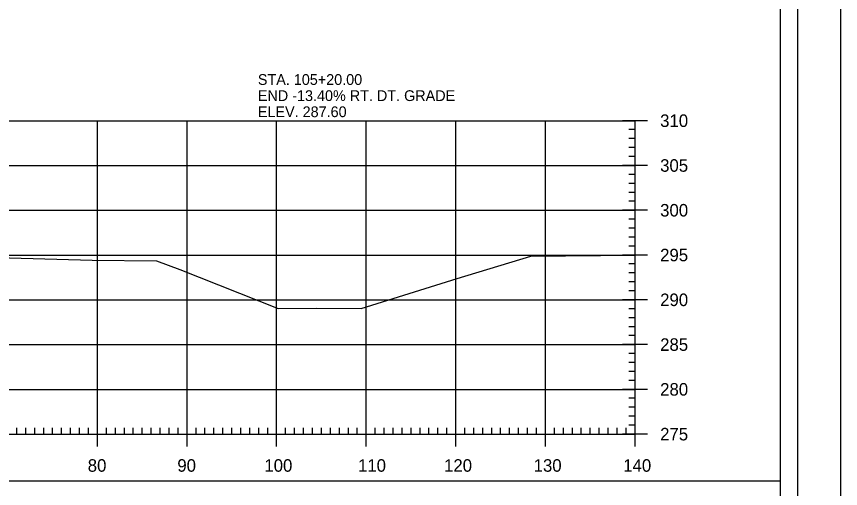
# Model space of a CAD drawing. Extents: x 1368713 to 1370673, y 380279 to 380950.
# Drawn here: x 1370223.2 to 1370315.2, y 380418.3 to 380471.1 of the extents above; entities that cross this region are included whole.
import ezdxf

# ---------------------------------------------------------------- set-up
doc = ezdxf.new("R2010")
doc.units = 0
for name, color, linetype in [('Notes', 7, 'Continuous'), ('R_Axis', 7, 'Continuous'), ('R_Axis Annot', 7, 'Continuous'), ('R_Border', 7, 'Continuous'), ('R_Exist Surface', 7, 'Continuous'), ('R_Grid', 7, 'Continuous'), ('R_No Plot', 7, 'Continuous')]:
    doc.layers.add(name, color=color, linetype=linetype)

msp = doc.modelspace()

# ---------------------------------------------------------------- linework, layer by layer
at = {"layer": 'R_Axis'}
for p, q in [((1370293.683, 380459.416), (1370290.883, 380459.416)), ((1370292.283, 380424.416), (1370292.283, 380459.416)), ((1370292.283, 380458.416), (1370291.583, 380458.416)), ((1370292.283, 380457.416), (1370291.583, 380457.416)), ((1370292.283, 380456.416), (1370291.583, 380456.416)), ((1370292.283, 380455.416), (1370291.583, 380455.416)), ((1370293.683, 380454.416), (1370290.883, 380454.416)), ((1370292.283, 380453.416), (1370291.583, 380453.416)), ((1370292.283, 380452.416), (1370291.583, 380452.416)), ((1370292.283, 380451.416), (1370291.583, 380451.416)), ((1370292.283, 380450.416), (1370291.583, 380450.416)), ((1370293.683, 380449.416), (1370290.883, 380449.416)), ((1370292.283, 380448.416), (1370291.583, 380448.416)), ((1370292.283, 380447.416), (1370291.583, 380447.416)), ((1370292.283, 380446.416), (1370291.583, 380446.416)), ((1370292.283, 380445.416), (1370291.583, 380445.416)), ((1370293.683, 380444.416), (1370290.883, 380444.416)), ((1370292.283, 380443.416), (1370291.583, 380443.416)), ((1370292.283, 380442.416), (1370291.583, 380442.416)), ((1370292.283, 380441.416), (1370291.583, 380441.416)), ((1370292.283, 380440.416), (1370291.583, 380440.416)), ((1370293.683, 380439.416), (1370290.883, 380439.416)), ((1370292.283, 380438.416), (1370291.583, 380438.416)), ((1370292.283, 380437.416), (1370291.583, 380437.416)), ((1370292.283, 380436.416), (1370291.583, 380436.416)), ((1370292.283, 380435.416), (1370291.583, 380435.416)), ((1370293.683, 380434.416), (1370290.883, 380434.416)), ((1370292.283, 380433.416), (1370291.583, 380433.416)), ((1370292.283, 380432.416), (1370291.583, 380432.416)), ((1370292.283, 380431.416), (1370291.583, 380431.416)), ((1370292.283, 380430.416), (1370291.583, 380430.416)), ((1370293.683, 380429.416), (1370290.883, 380429.416)), ((1370292.283, 380428.416), (1370291.583, 380428.416)), ((1370292.283, 380427.416), (1370291.583, 380427.416)), ((1370292.283, 380426.416), (1370291.583, 380426.416)), ((1370232.283, 380423.016), (1370232.283, 380425.816)), ((1370242.283, 380423.016), (1370242.283, 380425.816)), ((1370252.283, 380423.016), (1370252.283, 380425.816)), ((1370262.283, 380423.016), (1370262.283, 380425.816)), ((1370272.283, 380423.016), (1370272.283, 380425.816)), ((1370282.283, 380423.016), (1370282.283, 380425.816)), ((1370292.283, 380425.416), (1370291.583, 380425.416)), ((1370292.283, 380423.016), (1370292.283, 380425.816)), ((1370012.283, 380424.416), (1370292.283, 380424.416)), ((1370223.283, 380424.416), (1370223.283, 380425.116)), ((1370224.283, 380424.416), (1370224.283, 380425.116)), ((1370225.283, 380424.416), (1370225.283, 380425.116)), ((1370226.283, 380424.416), (1370226.283, 380425.116)), ((1370227.283, 380424.416), (1370227.283, 380425.116)), ((1370228.283, 380424.416), (1370228.283, 380425.116)), ((1370229.283, 380424.416), (1370229.283, 380425.116)), ((1370230.283, 380424.416), (1370230.283, 380425.116)), ((1370231.283, 380424.416), (1370231.283, 380425.116)), ((1370233.283, 380424.416), (1370233.283, 380425.116)), ((1370234.283, 380424.416), (1370234.283, 380425.116)), ((1370235.283, 380424.416), (1370235.283, 380425.116)), ((1370236.283, 380424.416), (1370236.283, 380425.116)), ((1370237.283, 380424.416), (1370237.283, 380425.116)), ((1370238.283, 380424.416), (1370238.283, 380425.116)), ((1370239.283, 380424.416), (1370239.283, 380425.116)), ((1370240.283, 380424.416), (1370240.283, 380425.116)), ((1370241.283, 380424.416), (1370241.283, 380425.116)), ((1370243.283, 380424.416), (1370243.283, 380425.116)), ((1370244.283, 380424.416), (1370244.283, 380425.116)), ((1370245.283, 380424.416), (1370245.283, 380425.116)), ((1370246.283, 380424.416), (1370246.283, 380425.116)), ((1370247.283, 380424.416), (1370247.283, 380425.116)), ((1370248.283, 380424.416), (1370248.283, 380425.116)), ((1370249.283, 380424.416), (1370249.283, 380425.116)), ((1370250.283, 380424.416), (1370250.283, 380425.116)), ((1370251.283, 380424.416), (1370251.283, 380425.116)), ((1370253.283, 380424.416), (1370253.283, 380425.116)), ((1370254.283, 380424.416), (1370254.283, 380425.116)), ((1370255.283, 380424.416), (1370255.283, 380425.116)), ((1370256.283, 380424.416), (1370256.283, 380425.116)), ((1370257.283, 380424.416), (1370257.283, 380425.116)), ((1370258.283, 380424.416), (1370258.283, 380425.116)), ((1370259.283, 380424.416), (1370259.283, 380425.116)), ((1370260.283, 380424.416), (1370260.283, 380425.116)), ((1370261.283, 380424.416), (1370261.283, 380425.116)), ((1370263.283, 380424.416), (1370263.283, 380425.116)), ((1370264.283, 380424.416), (1370264.283, 380425.116)), ((1370265.283, 380424.416), (1370265.283, 380425.116)), ((1370266.283, 380424.416), (1370266.283, 380425.116)), ((1370267.283, 380424.416), (1370267.283, 380425.116)), ((1370268.283, 380424.416), (1370268.283, 380425.116)), ((1370269.283, 380424.416), (1370269.283, 380425.116)), ((1370270.283, 380424.416), (1370270.283, 380425.116)), ((1370271.283, 380424.416), (1370271.283, 380425.116)), ((1370273.283, 380424.416), (1370273.283, 380425.116)), ((1370274.283, 380424.416), (1370274.283, 380425.116)), ((1370275.283, 380424.416), (1370275.283, 380425.116)), ((1370276.283, 380424.416), (1370276.283, 380425.116)), ((1370277.283, 380424.416), (1370277.283, 380425.116)), ((1370278.283, 380424.416), (1370278.283, 380425.116)), ((1370279.283, 380424.416), (1370279.283, 380425.116)), ((1370280.283, 380424.416), (1370280.283, 380425.116)), ((1370281.283, 380424.416), (1370281.283, 380425.116)), ((1370283.283, 380424.416), (1370283.283, 380425.116)), ((1370284.283, 380424.416), (1370284.283, 380425.116)), ((1370285.283, 380424.416), (1370285.283, 380425.116)), ((1370286.283, 380424.416), (1370286.283, 380425.116)), ((1370287.283, 380424.416), (1370287.283, 380425.116)), ((1370288.283, 380424.416), (1370288.283, 380425.116)), ((1370289.283, 380424.416), (1370289.283, 380425.116)), ((1370290.283, 380424.416), (1370290.283, 380425.116)), ((1370293.683, 380424.416), (1370290.883, 380424.416)), ((1370291.283, 380424.416), (1370291.283, 380425.116))]:
    msp.add_line(p, q, dxfattribs=at)
at = {"layer": 'R_Border'}
msp.add_line((1370310.463, 380314.416), (1370310.463, 380519.876), dxfattribs=at)
at = {"layer": 'R_Exist Surface'}
msp.add_lwpolyline([(1370127.849, 380444.919), (1370130.374, 380445.682), (1370140.627, 380448.69), (1370141.304, 380448.785), (1370141.852, 380448.857), (1370148.531, 380448.905), (1370151.928, 380448.923), (1370155.368, 380448.882), (1370161.602, 380448.773), (1370162.51, 380448.705), (1370163.958, 380448.527), (1370169.843, 380447.122), (1370176.724, 380445.458), (1370193.294, 380444.499), (1370206.6, 380444.552), (1370231.709, 380443.824), (1370238.873, 380443.758), (1370241.472, 380442.814), (1370252.467, 380438.447), (1370256.699, 380438.499), (1370261.723, 380438.461), (1370272.447, 380441.8), (1370280.645, 380444.286), (1370292.283, 380444.389)], dxfattribs=at)
at = {"layer": 'R_Grid'}
for p, q in [((1370012.283, 380459.416), (1370292.283, 380459.416)), ((1370232.283, 380424.416), (1370232.283, 380459.416)), ((1370242.283, 380424.416), (1370242.283, 380459.416)), ((1370252.283, 380424.416), (1370252.283, 380459.416)), ((1370262.283, 380424.416), (1370262.283, 380459.416)), ((1370272.283, 380424.416), (1370272.283, 380459.416)), ((1370282.283, 380424.416), (1370282.283, 380459.416)), ((1370292.283, 380424.416), (1370292.283, 380459.416)), ((1370012.283, 380454.416), (1370292.283, 380454.416)), ((1370012.283, 380449.416), (1370292.283, 380449.416)), ((1370012.283, 380444.416), (1370292.283, 380444.416)), ((1370012.283, 380439.416), (1370292.283, 380439.416)), ((1370012.283, 380434.416), (1370292.283, 380434.416)), ((1370012.283, 380429.416), (1370292.283, 380429.416)), ((1370012.283, 380424.416), (1370292.283, 380424.416))]:
    msp.add_line(p, q, dxfattribs=at)
at = {"layer": 'R_No Plot'}
for points in [[(1369981.875, 380523.77), (1370315.215, 380523.77), (1370315.215, 380310.433), (1369981.875, 380310.433)], [(1370308.463, 380419.146), (1369996.283, 380419.146), (1369996.283, 380517.876), (1370245.823, 380517.876), (1370245.823, 380507.996), (1370263.363, 380507.996), (1370287.463, 380507.996), (1370287.463, 380485.663), (1370308.463, 380485.663)], [(1369996.283, 380517.876), (1370245.823, 380517.876), (1370245.823, 380507.996), (1370263.363, 380507.996), (1370287.463, 380507.996), (1370287.463, 380485.663), (1370308.463, 380485.663), (1370308.463, 380316.416), (1369996.283, 380316.416)]]:
    msp.add_lwpolyline(points, close=True, dxfattribs=at)

# ---------------------------------------------------------------- texts
at = {"layer": 'Notes'}
for s, p in [('STA. 105+20.00', (1370250.186, 380463.414)), ('END -13.40% RT. DT. GRADE', (1370250.186, 380461.614)), ('ELEV. 287.60', (1370250.186, 380459.814))]:
    msp.add_text(s, height=1.2, dxfattribs=at).set_placement(p)
at = {"layer": 'R_Axis Annot'}
for s, p in [('310', (1370295.083, 380458.716)), ('305', (1370295.083, 380453.716)), ('300', (1370295.083, 380448.716)), ('295', (1370295.083, 380443.716)), ('290', (1370295.083, 380438.716)), ('285', (1370295.083, 380433.716)), ('280', (1370295.083, 380428.716)), ('275', (1370295.083, 380423.716)), ('80', (1370231.197, 380420.216)), ('90', (1370241.197, 380420.216)), ('100', (1370250.91, 380420.216)), ('110', (1370261.362, 380420.216)), ('120', (1370270.965, 380420.216)), ('130', (1370280.965, 380420.216)), ('140', (1370290.965, 380420.216))]:
    msp.add_text(s, height=1.4, dxfattribs=at).set_placement(p)

doc.saveas('drawing.dxf')
